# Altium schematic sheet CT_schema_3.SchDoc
size 559 x 419 mm
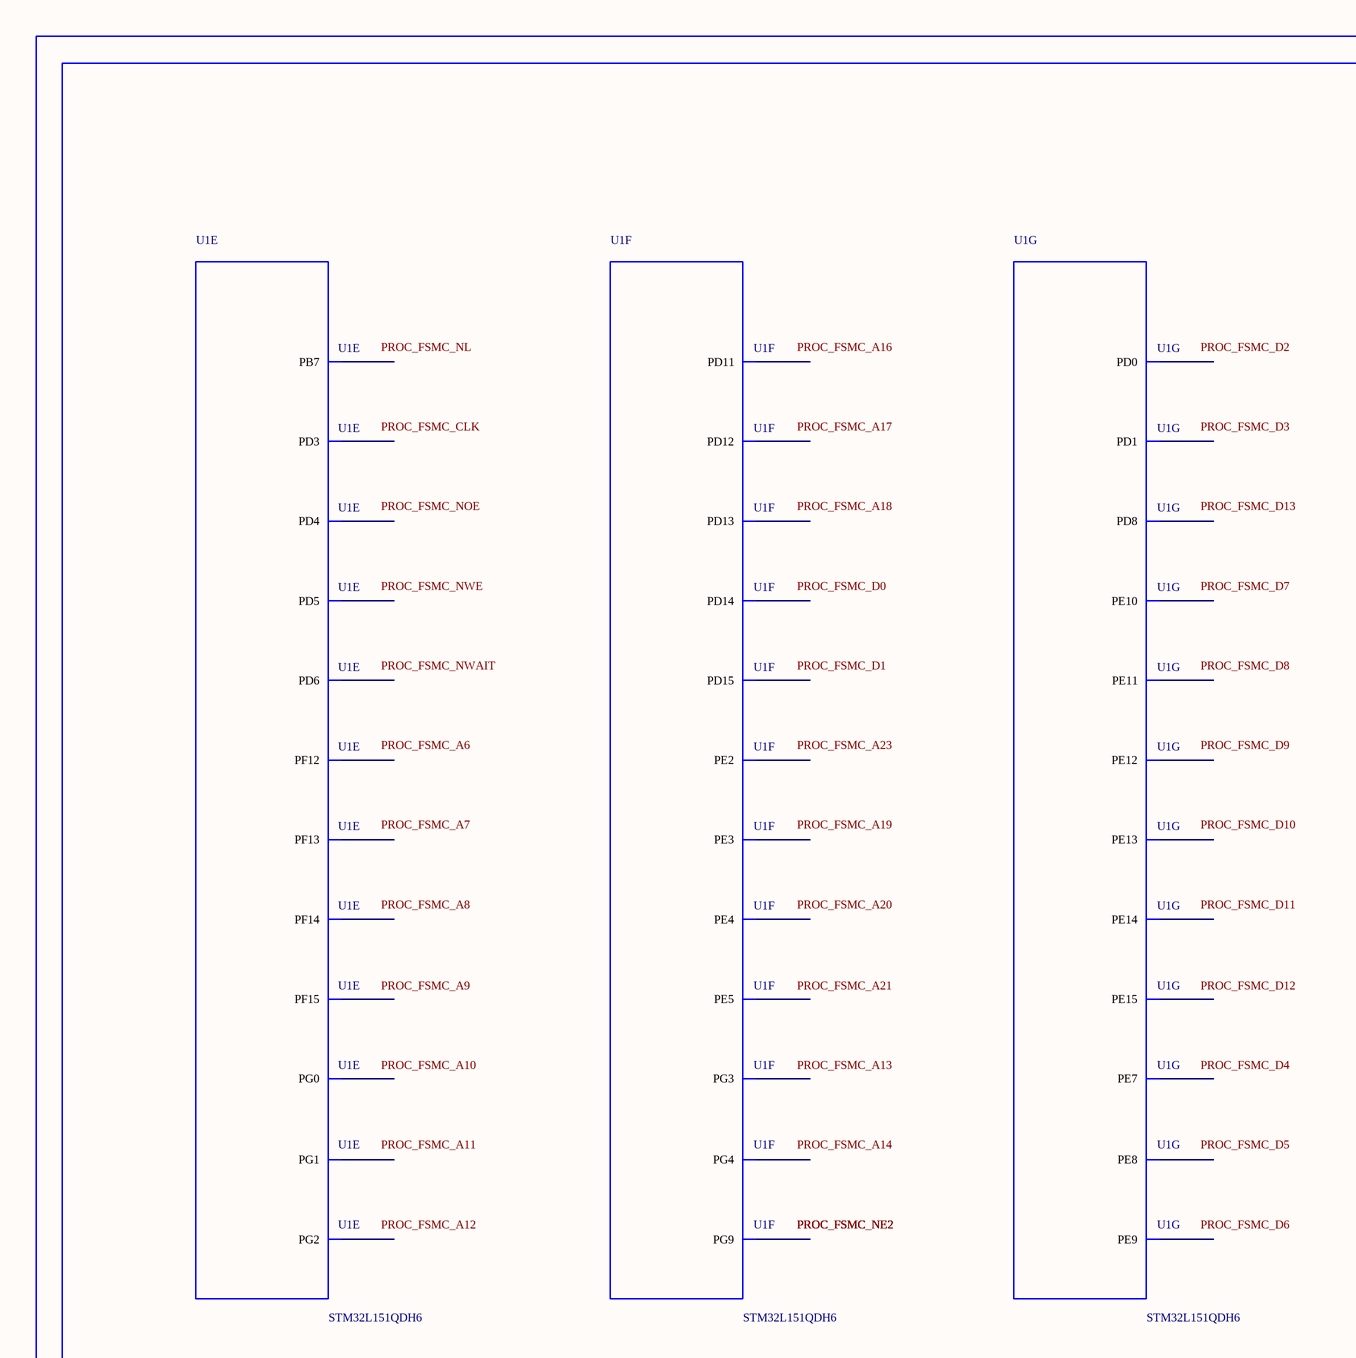
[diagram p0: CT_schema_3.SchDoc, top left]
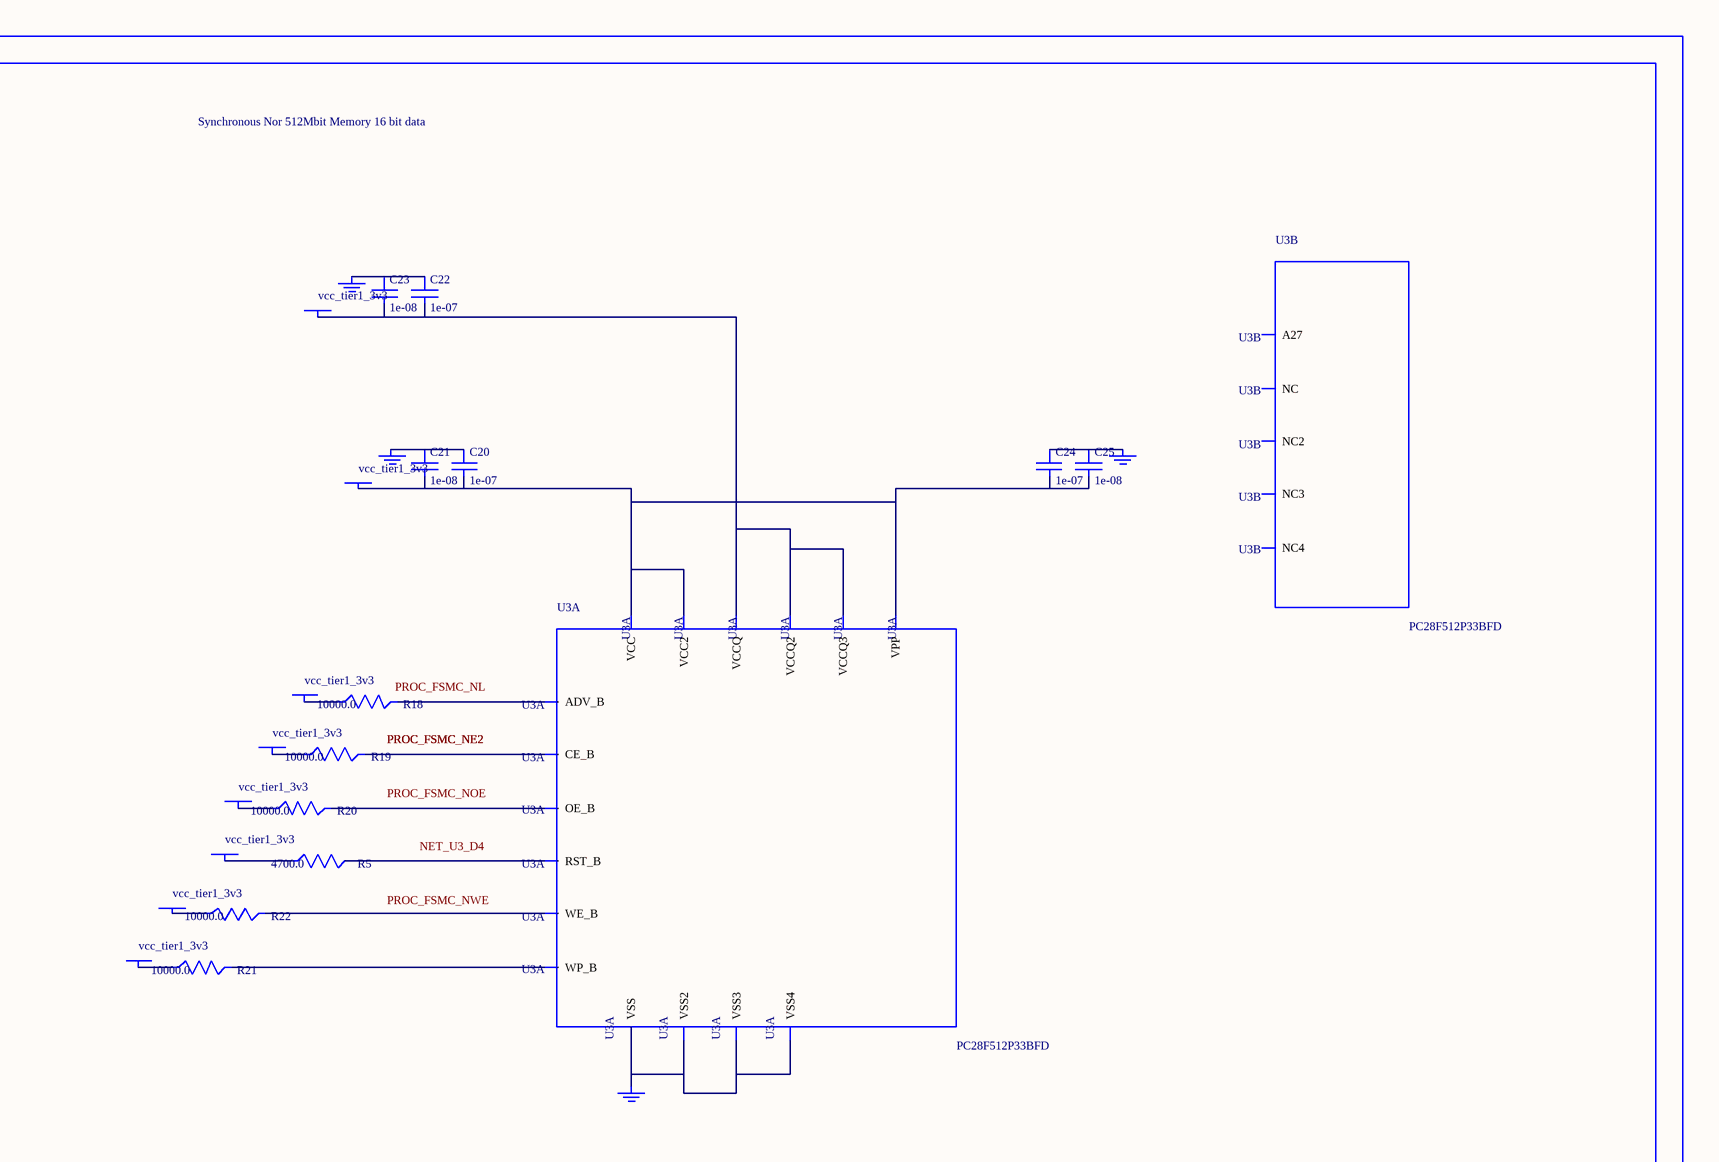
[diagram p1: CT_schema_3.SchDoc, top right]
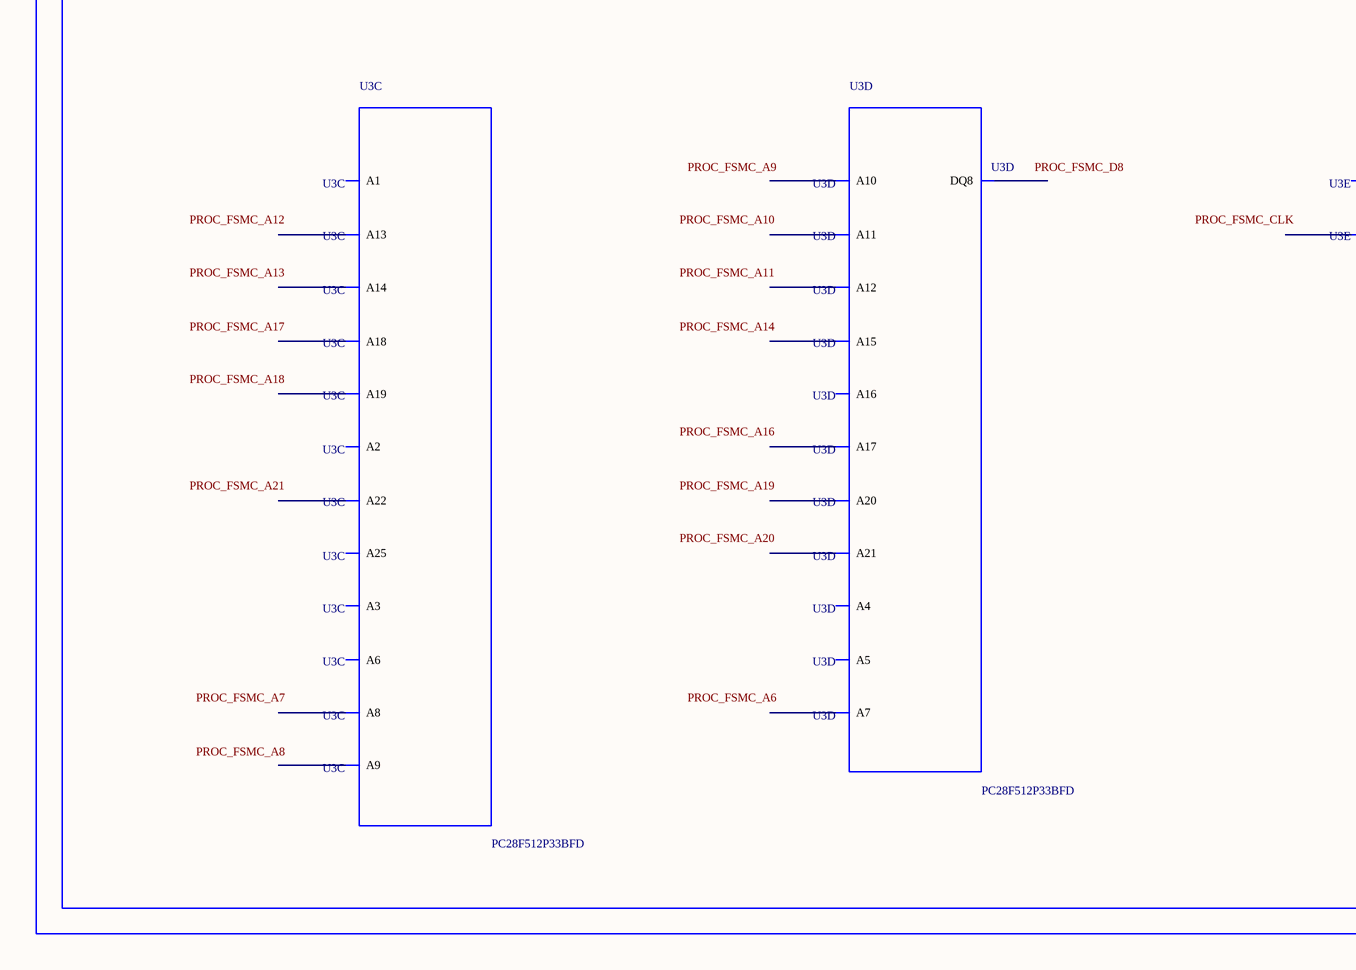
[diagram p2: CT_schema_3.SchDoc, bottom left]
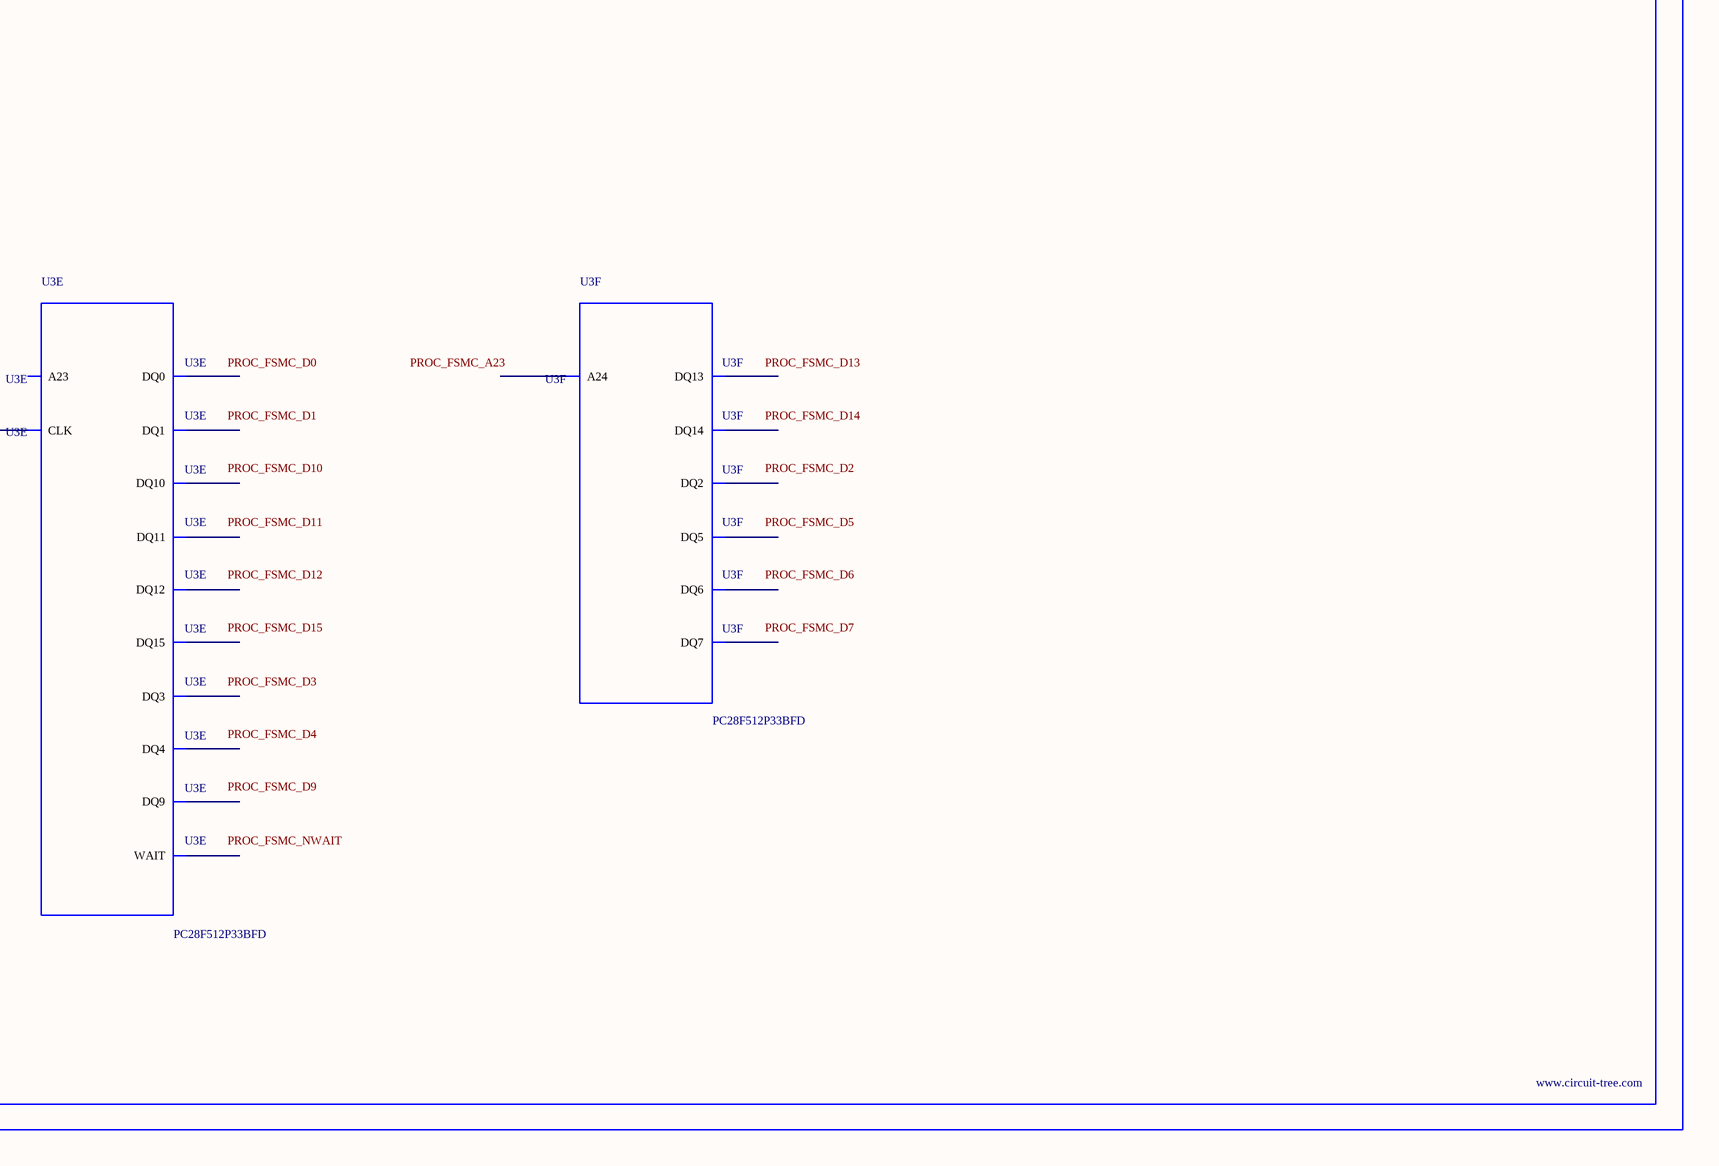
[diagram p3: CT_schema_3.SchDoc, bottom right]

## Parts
BORDER2  (no value)
C20  1e-07  [C0402]
C21  1e-08  [C0402]
C22  1e-07  [C0402]
C23  1e-08  [C0402]
C24  1e-07  [C0402]
C25  1e-08  [C0402]
GND_INSTANCE_2_0  (no value)
GND_INSTANCE_2_1  (no value)
GND_INSTANCE_2_2  (no value)
GND_INSTANCE_2_3  (no value)
POWER_INSTANCE_2_0  vcc_tier1_3v3
POWER_INSTANCE_2_1  vcc_tier1_3v3
POWER_INSTANCE_2_2  vcc_tier1_3v3
POWER_INSTANCE_2_3  vcc_tier1_3v3
POWER_INSTANCE_2_4  vcc_tier1_3v3
POWER_INSTANCE_2_5  vcc_tier1_3v3
POWER_INSTANCE_2_6  vcc_tier1_3v3
POWER_INSTANCE_2_7  vcc_tier1_3v3
R5  4700.0  [R0603]
R18  10000.0  [R0603]
R19  10000.0  [R0603]
R20  10000.0  [R0603]
R21  10000.0  [R0603]
R22  10000.0  [R0603]
U1  STM32L151QDH6  [UFBGA132]  (parts E,F,G of 9)
U3  PC28F512P33BFD  [PC28F512P33BFD]  (parts A,B,C,D,E,F of 6)

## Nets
NetC20_1: C20.1 C21.1 GND_INSTANCE_2_0.0(GND)
NetC20_2: C20.2 C21.2 C24.2 C25.2 POWER_INSTANCE_2_0.0(PWR) U3.A4(VPP) U3.A6(VCC) U3.H3(VCC2)
NetC22_1: C22.1 C23.1 GND_INSTANCE_2_1.0(GND)
NetC22_2: C22.2 C23.2 POWER_INSTANCE_2_1.0(PWR) U3.D5(VCCQ) U3.D6(VCCQ2) U3.G4(VCCQ3)
NetC24_1: C24.1 C25.1 GND_INSTANCE_2_2.0(GND)
NetGND_INSTANCE_2_3_0: GND_INSTANCE_2_3.0(GND) U3.B2(VSS) U3.H2(VSS2) U3.H4(VSS3) U3.H6(VSS4)
NetPOWER_INSTANCE_2_2_0: POWER_INSTANCE_2_2.0(PWR) R18.1
NetPOWER_INSTANCE_2_3_0: POWER_INSTANCE_2_3.0(PWR) R19.1
NetPOWER_INSTANCE_2_4_0: POWER_INSTANCE_2_4.0(PWR) R20.1
NetPOWER_INSTANCE_2_5_0: POWER_INSTANCE_2_5.0(PWR) R21.1
NetPOWER_INSTANCE_2_6_0: POWER_INSTANCE_2_6.0(PWR) R22.1
NetPOWER_INSTANCE_2_7_0: POWER_INSTANCE_2_7.0(PWR) R5.1
NetR5_2: R5.2 U3.D4(RST_B)
NetR18_2: R18.2 U3.F6(ADV_B)
NetR19_2: R19.2 U3.B4(CE_B)
NetR20_2: R20.2 U3.F8(OE_B)
NetR21_2: R21.2 U3.C6(WP_B)
NetR22_2: R22.2 U3.G8(WE_B)

Not connected (* = marked no-connect by the designer): U1 A1(PE3) A6(PD5) B1(PE4) B2(PE2) B4(PB7) B6(PD6) B7(PD4) B8(PD3) B9(PD1) C2(PE5) C9(PD0) D9(PG9) F9(PG3) F10(PG4) G9(PG1) G10(PG2) H9(PG0) H10(PD15) H11(PD14) H12(PD13) J7(PF12) J8(PF14) J9(PF15) J10(PD12) J11(PD11) K7(PF13) K9(PD8) L7(PE8) L8(PE10) L9(PE12) M7(PE7) M8(PE9) M9(PE11) M10(PE13) M11(PE14) M12(PE15); U3 A1 A2(A6) A3(A8) A5(A13) A7(A18) A8(A22) B1(A2) B3(A9) B5(A14) B6(A25) B7(A19) B8(NC) C1(A3) C2(A7) C3(A10) C4(A12) C5(A15) C7(A20) C8(A21) D1(A4) D2(A5) D3(A11) D7(A16) D8(A17) E1(DQ8) E2(DQ1) E3(DQ9) E4(DQ3) E5(DQ4) E6(CLK) E7(DQ15) E8(NC2) F1(NC3) F2(DQ0) F3(DQ10) F4(DQ11) F5(DQ12) F7(WAIT) G1(A23) G2(NC4) G3(DQ2) G5(DQ5) G6(DQ6) G7(DQ14) H1(A27) H5(DQ13) H7(DQ7) H8(A24)

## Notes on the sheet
- Labels drawn without touching a wire or pin: NET_U3_D4, PROC_FSMC_A6, PROC_FSMC_A7, PROC_FSMC_A8, PROC_FSMC_A9, PROC_FSMC_A10, PROC_FSMC_A11, PROC_FSMC_A12, PROC_FSMC_A13, PROC_FSMC_A14, PROC_FSMC_A16, PROC_FSMC_A17, PROC_FSMC_A18, PROC_FSMC_A19, PROC_FSMC_A20, PROC_FSMC_A21, PROC_FSMC_A23, PROC_FSMC_CLK, PROC_FSMC_D0, PROC_FSMC_D1, PROC_FSMC_D2, PROC_FSMC_D3, PROC_FSMC_D4, PROC_FSMC_D5, PROC_FSMC_D6, PROC_FSMC_D7, PROC_FSMC_D8, PROC_FSMC_D9, PROC_FSMC_D10, PROC_FSMC_D11, PROC_FSMC_D12, PROC_FSMC_D13, PROC_FSMC_D14, PROC_FSMC_D15, PROC_FSMC_NL, PROC_FSMC_NOE, PROC_FSMC_NWAIT, PROC_FSMC_NWE

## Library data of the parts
BORDER2 = BORDER_PAGE2
C20 C22 C24 = C0402C104K3RACTU
C21 C23 C25 = C0402C103K3RAC
GND_INSTANCE_2_0-GND_INSTANCE_2_3 = GND
POWER_INSTANCE_2_0-POWER_INSTANCE_2_7 = PWR
R5 = RC0603JR-074K7L
R18-R22 = RC0603JR-0710KL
